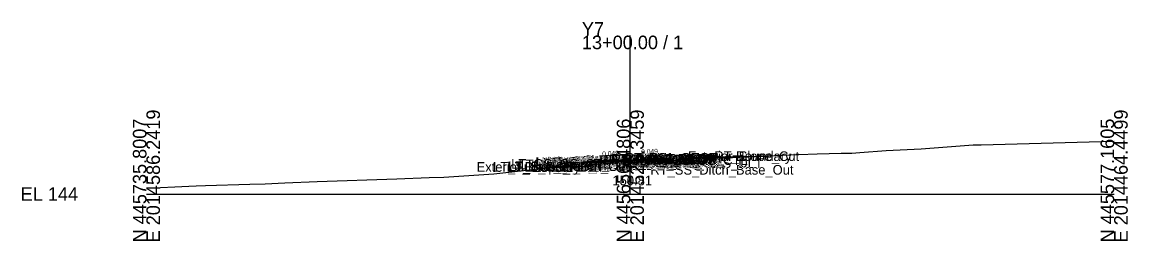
# Model space of a CAD drawing. Extents: x -26 to 203, y -10 to 7527.
# Drawn here: x -25.7 to 202.8, y 5990.3 to 6035.6 of the extents above; entities that cross this region are included whole.
import ezdxf

# ---------------------------------------------------------------- set-up
doc = ezdxf.new("R2010")
doc.units = 0
for name, color, linetype in [('Exist CMT Pavement', 7, 'Continuous'), ('Exist Cross Section Cell', 7, 'Continuous'), ('Exist XS Center Line Elevation Label', 7, 'Continuous'), ('Exist XS Ground Line', 7, 'Continuous'), ('Prop CMT Pvmt Course 1', 7, 'Continuous'), ('Prop CMT Pvmt Course 1 Wedge', 7, 'Continuous'), ('Prop CMT Pvmt Course 2', 7, 'Continuous'), ('Prop CMT Pvmt Course 2 Wedge', 7, 'Continuous'), ('Prop CMT Pvmt Course 3', 7, 'Continuous'), ('Prop CMT Pvmt Course 3 Wedge', 7, 'Continuous'), ('Prop CMT Pvmt Surface', 7, 'Continuous'), ('Prop CMT Pvmt Surface Shoulder', 7, 'Continuous'), ('Prop CMT Pvmt Wedge Surface 1', 7, 'Continuous'), ('Prop CMT Pvmt Wedge Surface 2', 7, 'Continuous'), ('Prop CMT Pvmt Wedge Surface 3', 7, 'Continuous'), ('Prop CMT Shld Paved Course 1', 7, 'Continuous'), ('Prop CMT Shld Paved Course 2', 7, 'Continuous'), ('Prop CMT Shld Paved Course 3', 7, 'Continuous'), ('Prop CMT Slope Grass', 7, 'Continuous'), ('Prop CMT Subgrade Earthwork', 7, 'Continuous'), ('Prop XS Earthwork Shape', 7, 'Continuous'), ('Prop XS SE Text', 7, 'Continuous'), ('Prop XS Side Slope Text', 7, 'Continuous'), ('Scratch_Level_0', 7, 'Continuous')]:
    doc.layers.add(name, color=color, linetype=linetype)

msp = doc.modelspace()

# ---------------------------------------------------------------- linework, layer by layer
at = {"layer": 'Exist CMT Pavement'}
msp.add_lwpolyline([(93, 6006.57), (94.43, 6006.62), (99, 6006.78), (100, 6006.81), (102.61, 6006.9), (106.31, 6007.02)], dxfattribs=at)
at = {"layer": 'Exist Cross Section Cell'}
for p, q in [((100, 6000), (100, 6032.78)), ((0, 6000), (100, 6000)), ((100, 6000), (200, 6000))]:
    msp.add_line(p, q, dxfattribs=at)
at = {"layer": 'Exist XS Ground Line'}
msp.add_lwpolyline([(0, 6001.19), (8.78, 6001.66), (10.26, 6001.69), (12.19, 6001.76), (21.39, 6002.07), (24.52, 6002.13), (28.61, 6002.31), (35.27, 6002.62), (51.77, 6003.17), (58.44, 6003.42), (61.46, 6003.52), (71.82, 6004.16), (81.65, 6005.32), (85.32, 6005.73), (89.92, 6006.23), (90.24, 6006.38), (90.64, 6006.48), (94.43, 6006.62), (99, 6006.78), (100, 6006.81), (102.61, 6006.9), (107.9, 6007.07), (108.31, 6007.21), (108.72, 6007), (109.77, 6007.05), (111.31, 6007.12), (124.38, 6007.68), (127.15, 6007.81), (131.52, 6008.02), (134.86, 6008.16), (138.65, 6008.32), (143.58, 6008.43), (145.78, 6008.49), (147.47, 6008.61), (152.91, 6009.01), (160.11, 6009.39), (170.87, 6010.22), (172.52, 6010.21), (197.33, 6010.89), (200, 6010.93)], dxfattribs=at)
at = {"layer": 'Prop CMT Pvmt Course 1'}
for points in [[(100, 6007.1), (92, 6006.71)], [(92, 6006.71), (92, 6006.46)], [(92, 6006.46), (93, 6006.51)], [(93, 6006.64), (100, 6006.98)], [(93, 6006.51), (93, 6006.64)], [(100, 6007.1), (108.12, 6007.5)], [(106.31, 6007.28), (100, 6006.98)], [(100, 6006.85), (100, 6007.1)], [(100, 6006.85), (100, 6007.1)], [(100, 6006.98), (100, 6006.85), (100, 6006.85)], [(100, 6006.98), (100, 6006.85), (100, 6006.85)], [(106.31, 6007.16), (106.31, 6007.28)], [(108.12, 6007.25), (106.31, 6007.16)], [(108.12, 6007.5), (108.12, 6007.25)]]:
    msp.add_lwpolyline(points, dxfattribs=at)
at = {"layer": 'Prop CMT Pvmt Course 1 Wedge'}
for points in [[(100, 6006.98), (93, 6006.64)], [(100, 6006.98), (106.31, 6007.28)]]:
    msp.add_lwpolyline(points, dxfattribs=at)
at = {"layer": 'Prop CMT Pvmt Course 2'}
for points in [[(93, 6006.51), (92, 6006.46)], [(92, 6006.46), (92, 6006.13)], [(92, 6006.13), (93, 6006.18)], [(93, 6006.18), (93, 6006.51)], [(106.31, 6007.16), (108.12, 6007.25)], [(106.31, 6006.83), (106.31, 6007.16)], [(108.12, 6006.91), (106.31, 6006.83)], [(108.12, 6007.25), (108.12, 6006.91)]]:
    msp.add_lwpolyline(points, dxfattribs=at)
at = {"layer": 'Prop CMT Pvmt Course 2 Wedge'}
for points in [[(100, 6006.85), (93, 6006.51)], [(100, 6006.85), (106.31, 6007.16)]]:
    msp.add_lwpolyline(points, dxfattribs=at)
at = {"layer": 'Prop CMT Pvmt Course 3'}
for points in [[(93, 6006.18), (92, 6006.13)], [(92, 6006.13), (92, 6005.8)], [(92, 6005.8), (93, 6005.84)], [(93, 6005.84), (93, 6006.18)], [(106.31, 6006.83), (108.12, 6006.91)], [(106.31, 6006.49), (106.31, 6006.83)], [(108.12, 6006.58), (106.31, 6006.49)], [(108.12, 6006.91), (108.12, 6006.58)]]:
    msp.add_lwpolyline(points, dxfattribs=at)
at = {"layer": 'Prop CMT Pvmt Course 3 Wedge'}
for points in [[(100, 6006.52), (93, 6006.18)], [(100, 6006.52), (106.31, 6006.83)]]:
    msp.add_lwpolyline(points, dxfattribs=at)
at = {"layer": 'Prop CMT Pvmt Surface'}
for points in [[(100, 6007.1), (92, 6006.71)], [(100, 6007.1), (108.12, 6007.5)]]:
    msp.add_lwpolyline(points, dxfattribs=at)
at = {"layer": 'Prop CMT Pvmt Surface Shoulder'}
for points in [[(92, 6006.71), (92, 6006.71)], [(108.12, 6007.5), (108.12, 6007.5)]]:
    msp.add_lwpolyline(points, dxfattribs=at)
at = {"layer": 'Prop CMT Pvmt Wedge Surface 1'}
for points in [[(92, 6006.46), (92, 6006.71)], [(93, 6006.51), (92, 6006.46)], [(100, 6006.98), (93, 6006.64)], [(93, 6006.64), (93, 6006.51)], [(100, 6006.98), (106.31, 6007.28)], [(106.31, 6007.28), (106.31, 6007.16)], [(106.31, 6007.16), (108.12, 6007.25)], [(108.12, 6007.25), (108.12, 6007.5)]]:
    msp.add_lwpolyline(points, dxfattribs=at)
at = {"layer": 'Prop CMT Pvmt Wedge Surface 2'}
for points in [[(100, 6006.85), (92, 6006.46)], [(92, 6006.46), (92, 6006.71)], [(100, 6006.85), (108.12, 6007.25)], [(108.12, 6007.25), (108.12, 6007.5)]]:
    msp.add_lwpolyline(points, dxfattribs=at)
at = {"layer": 'Prop CMT Pvmt Wedge Surface 3'}
for points in [[(92, 6006.13), (92, 6006.71)], [(100, 6006.52), (92, 6006.13)], [(100, 6006.52), (108.12, 6006.91)], [(108.12, 6006.91), (108.12, 6007.5)]]:
    msp.add_lwpolyline(points, dxfattribs=at)
at = {"layer": 'Prop CMT Shld Paved Course 1'}
for points in [[(92, 6006.71), (91.75, 6006.46)], [(91.75, 6006.46), (92, 6006.46)], [(92, 6006.71), (92, 6006.71)], [(92, 6006.46), (92, 6006.71)], [(108.12, 6007.5), (108.12, 6007.5)], [(108.12, 6007.5), (108.38, 6007.24)], [(108.12, 6007.25), (108.12, 6007.5)], [(108.38, 6007.24), (108.12, 6007.25)]]:
    msp.add_lwpolyline(points, dxfattribs=at)
at = {"layer": 'Prop CMT Shld Paved Course 2'}
for points in [[(92, 6006.46), (91.75, 6006.46), (91.41, 6006.12)], [(91.41, 6006.12), (92, 6006.13)], [(92, 6006.13), (92, 6006.46)], [(108.12, 6007.25), (108.38, 6007.24), (108.72, 6006.9)], [(108.12, 6006.91), (108.12, 6007.25)], [(108.72, 6006.9), (108.12, 6006.91)]]:
    msp.add_lwpolyline(points, dxfattribs=at)
at = {"layer": 'Prop CMT Shld Paved Course 3'}
for points in [[(92, 6006.13), (91.41, 6006.12), (91.07, 6005.78)], [(92, 6005.8), (92, 6006.13)], [(108.12, 6006.58), (108.12, 6006.91)], [(108.12, 6006.91), (108.72, 6006.9), (109.06, 6006.56)], [(109.56, 6006.55), (108.12, 6006.58)], [(90.57, 6005.77), (92, 6005.8)]]:
    msp.add_lwpolyline(points, dxfattribs=at)
at = {"layer": 'Prop CMT Slope Grass'}
for points in [[(92, 6006.71), (86, 6006.23), (84.09, 6005.6)], [(108.12, 6007.5), (127.77, 6007.84)]]:
    msp.add_lwpolyline(points, dxfattribs=at)
at = {"layer": 'Prop CMT Subgrade Earthwork'}
msp.add_line((109.56, 6006.55), (114.55, 6007.61), dxfattribs=at)
for points in [[(93, 6005.84), (92, 6005.8)], [(93, 6005.84), (93, 6006.57)], [(106.31, 6006.49), (106.31, 6007.02)], [(106.31, 6006.49), (108.12, 6006.58)], [(108.12, 6006.58), (109.56, 6006.55)], [(90.57, 6005.77), (84.23, 6005.64)], [(92, 6005.8), (90.57, 6005.77)]]:
    msp.add_lwpolyline(points, dxfattribs=at)
at = {"layer": 'Prop XS Earthwork Shape'}
for points in [[(93, 6005.84), (93, 6006.57), (90.64, 6006.48), (90.24, 6006.38), (89.92, 6006.23), (85.32, 6005.73), (84.55, 6005.65), (90.57, 6005.77), (92, 6005.8)], [(108.31, 6007.21), (108.72, 6007), (109.77, 6007.05), (111.31, 6007.12), (112.27, 6007.16), (112.5, 6007.17), (109.56, 6006.55), (108.12, 6006.58), (106.31, 6006.49), (106.31, 6007.02), (107.9, 6007.07)], [(112.5, 6007.17), (114.55, 6007.61), (127.77, 6007.84)], [(84.23, 6005.64), (84.09, 6005.6), (84.55, 6005.65)]]:
    msp.add_lwpolyline(points, close=True, dxfattribs=at)

# ---------------------------------------------------------------- texts
at = {"layer": 'Exist Cross Section Cell'}
for s, p in [('Y7', (90, 6032.78)), ('13+00.00 / 1', (90, 6029.98)), ('EL 144', (-26, 5998.6))]:
    msp.add_text(s, height=2.8, dxfattribs=at).set_placement(p)
for s, p in [('E 2014586.2419', (2.8, 5990)), ('E 2014525.3459', (102.8, 5990)), ('E 2014464.4499', (202.8, 5990)), ('N 445735.8007', (0, 5990)), ('N 445656.4806', (100, 5990)), ('N 445577.1605', (200, 5990))]:
    msp.add_text(s, height=2.8, rotation=90, dxfattribs=at).set_placement(p)
at = {"layer": 'Exist XS Center Line Elevation Label'}
msp.add_text('150.81', height=2, dxfattribs=at).set_placement((96.32, 6001.81))
at = {"layer": 'Prop XS SE Text'}
for p in [(94.22, 6007.82), (102.28, 6008.21)]:
    msp.add_text('0.049', height=1, rotation=2.7845, dxfattribs=at).set_placement(p)
at = {"layer": 'Prop XS Side Slope Text'}
msp.add_text('3:1', height=1, rotation=18.4332, dxfattribs=at).set_placement((84.06, 6006.37))
at = {"layer": 'Scratch_Level_0'}
for s, p in [('RT_Sub Tie Out', (93.6, 6006.02)), ('PV1_PGL', (94.47, 6006.1)), ('RT_PV2_OEEOP', (95.57, 6006.16)), ('RT_PV1_OEEOP', (96.14, 6006.28)), ('RT_PV2_OEOT', (98.25, 6006.25)), ('RT_PS2_OEOP', (98.57, 6006.24)), ('RT_PV1_OEOT', (98.82, 6006.5)), ('RT_PS1_OEOP', (98.88, 6006.5)), ('Exterior Boundary', (111.91, 6006.84)), ('RT_Slope_Cut', (117.36, 6006.84)), ('Exterior Boundary', (68.23, 6004.6)), ('LT_Sub_OSS_DLT', (71.63, 6004.64)), ('LT_Slope_Fill', (74.61, 6004.6)), ('LT_Sub_Trench_Out', (74.77, 6004.77)), ('LT_GS_OS_CTL', (75.37, 6005.23)), ('LT_PS3_Shelf_Out', (76.89, 6005.11)), ('LT_Sub Tie Out', (80.34, 6005.57)), ('LT_PV_OEEOP_EG', (80.55, 6005.57)), ('LT_PS3_OEOP', (81.64, 6005.12)), ('LT_PS2_OEOP', (81.98, 6005.46)), ('LT_Sub_OEOT', (82.08, 6004.8)), ('LT_PV2_OEOT', (82.18, 6005.46)), ('LT_PV3_OEOT', (82.18, 6005.13)), ('LT_Sub_OEEOP', (82.22, 6004.84)), ('LT_PV2_OEEOP', (82.31, 6005.51)), ('LT_PV3_OEEOP', (82.31, 6005.18)), ('LT_PV1_OEOT', (82.74, 6005.71)), ('LT_PS1_OEOP', (82.81, 6005.71)), ('LT_PV1_OEEOP', (82.88, 6005.64)), ('RT_PV_IEEOP_EG', (88.14, 6005.81)), ('LT_PV_IEEOP_EG', (88.19, 6005.81)), ('RT_PV2_IEEOP', (89.91, 6005.85)), ('RT_PV3_IEEOP', (89.91, 6005.52)), ('LT_PV2_IEEOP', (89.95, 6005.85)), ('LT_PV3_IEEOP', (89.95, 6005.52)), ('RT_PV1_IEEOP', (90.47, 6005.98)), ('LT_PV1_IEEOP', (90.52, 6005.98)), ('RT_Sub_Trench_Out', (93.71, 6005.55)), ('RT_PV_OEEOP_EG', (93.8, 6006.02)), ('PV2_PGL', (93.91, 6005.85)), ('RT_PS3_Shelf_Out', (95.15, 6005.89)), ('RT_Sub_OEEOP', (95.48, 6005.49)), ('RT_PV3_OEEOP', (95.57, 6005.83)), ('RT_Sub_OEOT', (98.15, 6005.58)), ('RT_PV3_OEOT', (98.25, 6005.91)), ('RT_PS3_OEOP', (98.91, 6005.9)), ('RT_GS_OS_CTL', (103.44, 6006.02)), ('RT_Sub_OSS_DLT', (103.9, 6005.41)), ('RT_SS_Ditch_Base_Out', (104.15, 6004.02))]:
    msp.add_text(s, height=2, dxfattribs=at).set_placement(p)

doc.saveas('drawing.dxf')
